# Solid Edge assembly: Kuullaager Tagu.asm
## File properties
Author: Türk
Template: Iso Assembly.asm
Last saved by: Türk
Revision: 7
Application: Solid Edge
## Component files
lss.par
el.par
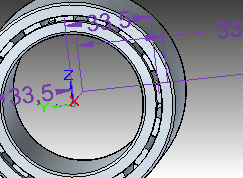
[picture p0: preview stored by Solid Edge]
